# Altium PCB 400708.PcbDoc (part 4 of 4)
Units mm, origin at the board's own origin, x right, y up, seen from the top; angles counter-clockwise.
Board outline 117 x 63.5 mm, 4 copper layers (Top Layer, Mid-Layer 1, Mid-Layer 2, Bottom Layer), stack 1.556 mm thick; 226 components, 168 nets, 912 pads, 2002 vias.
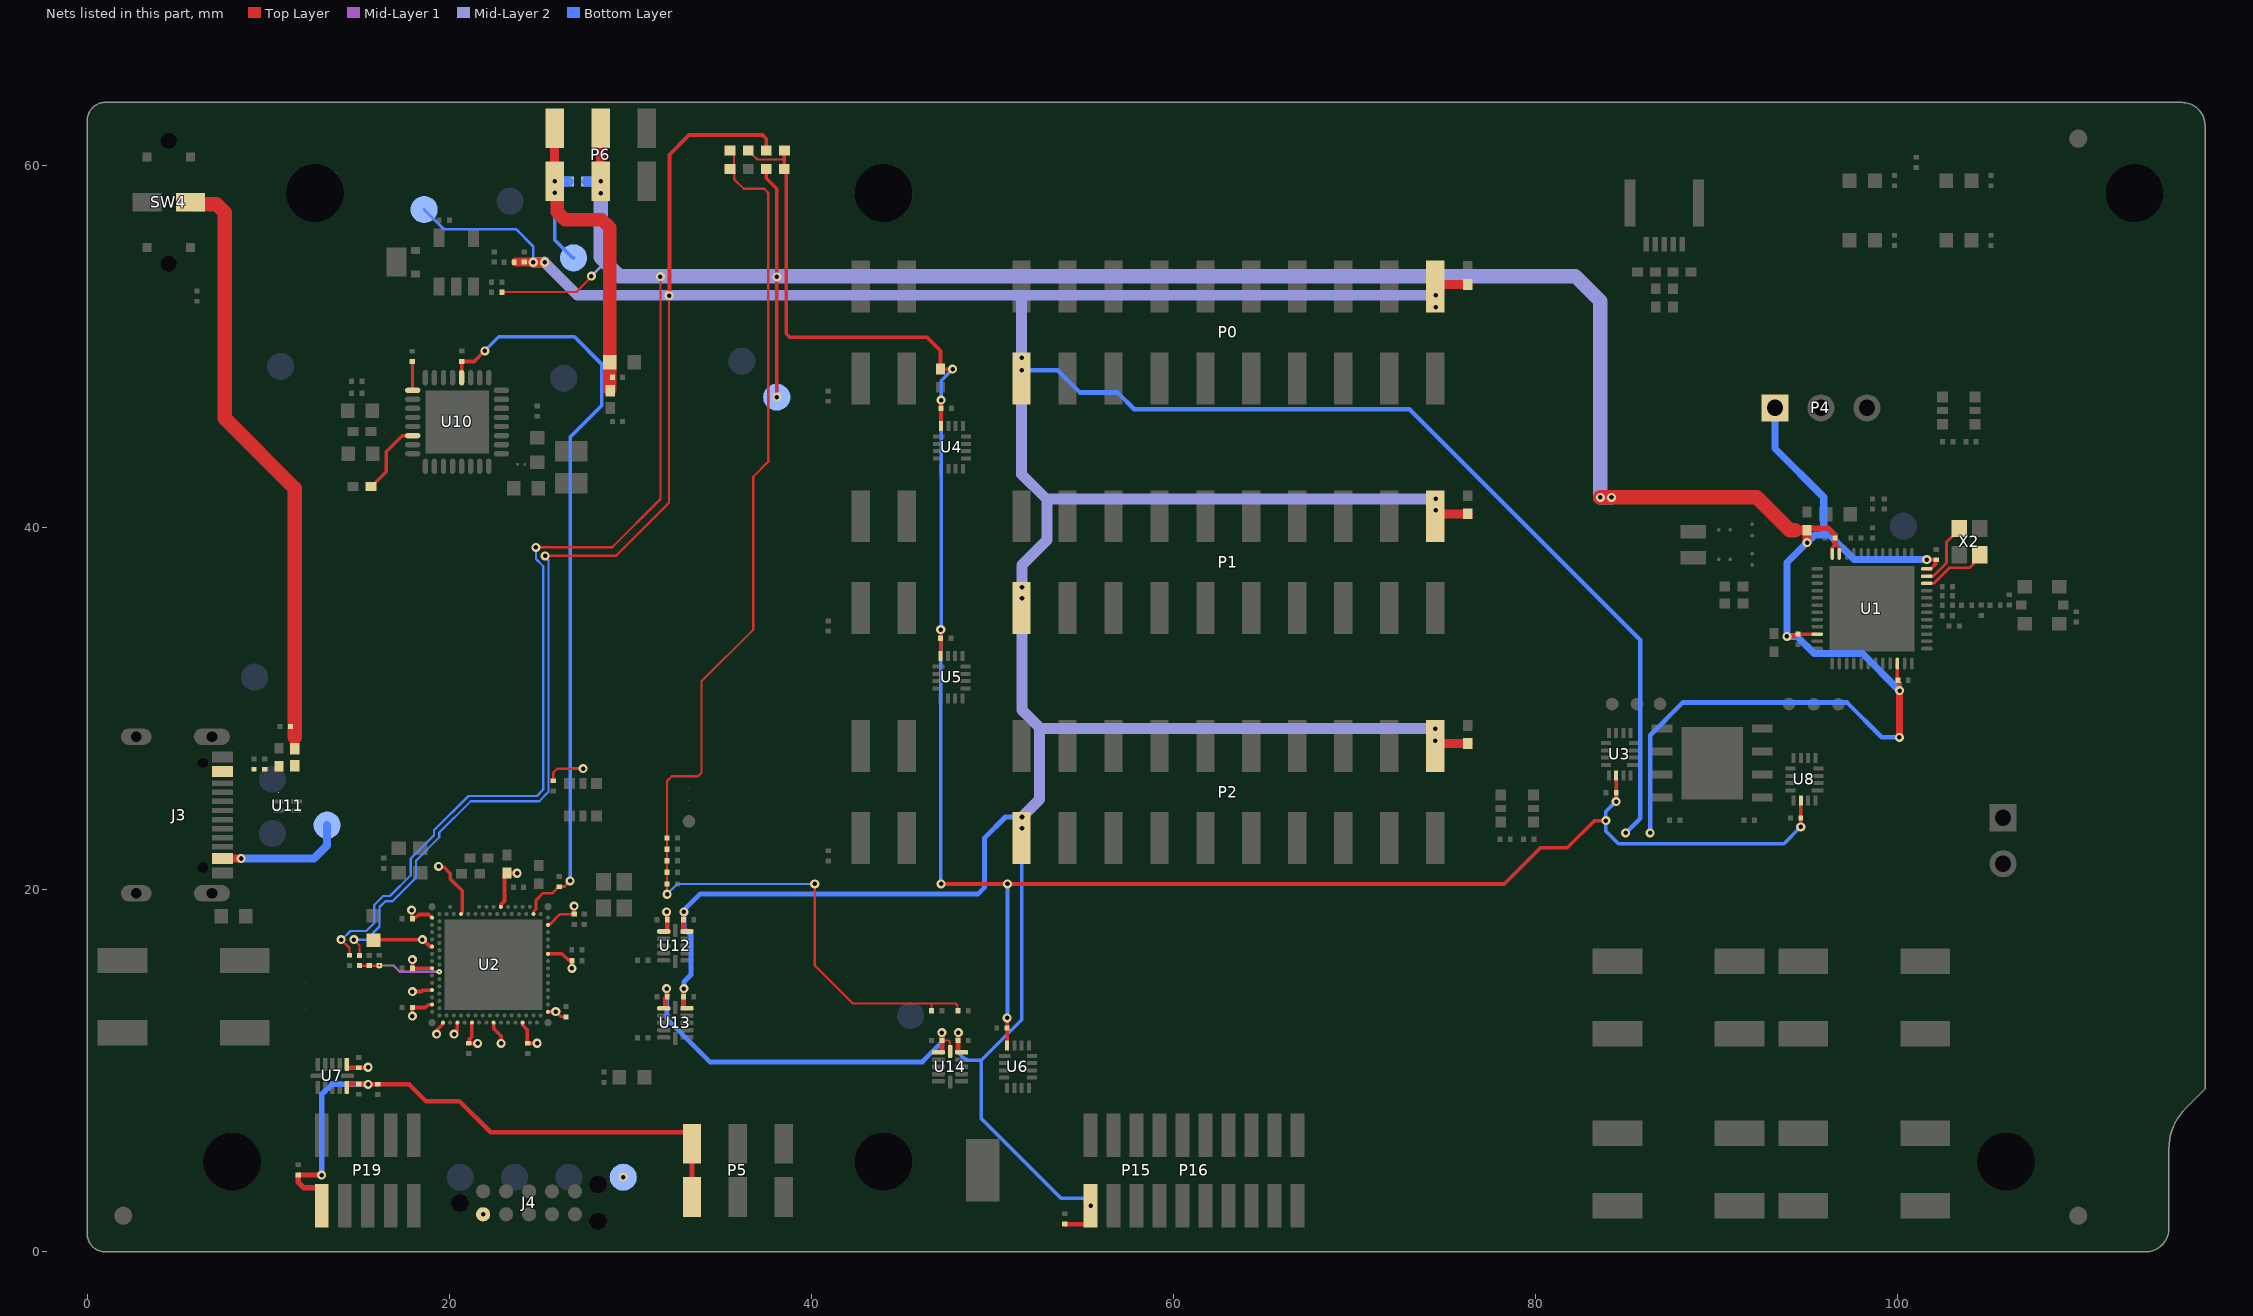
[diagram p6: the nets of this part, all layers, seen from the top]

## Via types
v1: diameter 0.5, hole 0.25, Top Layer to Bottom Layer, tented both sides, 1905 vias
v2: diameter 0.3, hole 0.1, Top Layer to Mid-Layer 1, tented top, 77 vias
v3: diameter 0.3, hole 0.1, Top Layer to Mid-Layer 1, tented both sides, 20 vias

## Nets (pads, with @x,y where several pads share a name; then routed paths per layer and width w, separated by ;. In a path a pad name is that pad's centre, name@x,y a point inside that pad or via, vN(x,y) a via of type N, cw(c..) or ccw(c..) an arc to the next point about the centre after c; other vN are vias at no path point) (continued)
VBUS:IN1: C30.1 C47.2 C48.2 FB2.1 J3.A4 J3.A9 TP16.1 U11.1 | length 7.2
  Top Layer w0.45: J3.A9@7.485,21.734 7.487,21.732 v1(8.517,21.732)
  Bottom Layer w0.45: v1(8.517,21.732) 8.519,21.73 12.548,21.73 13.263,22.446 TP16.1@13.263,23.571
VBUS:IN2: C46.2 FB2.2 SW4.5 | length 33.3
  Top Layer w0.5: FB2.2@11.475,27.8 11.475,28.423
  Top Layer w0.8: SW4.5@5.721,57.988 5.821,57.888 7.131,57.888 7.6,57.42 7.6,46.05 11.475,42.175 11.475,29.025 11.475,28.423
VBUSOUT: C68.2 U10.22 | length 4.1
  Top Layer w0.2: C68.2@15.702,42.275 16.525,43.098 16.525,44.202 17.408,45.086 17.981,45.086 U10.22@17.992,45.096
VDD: C25.2 C58.1 FB3.2 P6.3 R24.2 TP9.1 | length 22.4
  Top Layer w0.3: v1(25.832,58.5) v1(25.832,59.141)
  Top Layer w0.5: v1(25.832,59.141) P6.3@25.832,62.071
  Top Layer w0.75: v1(25.832,58.5) 25.888,58.5 25.967,58.421 25.967,57.464 26.406,57.025 28.436,57.025 28.875,56.586 C58.1@28.875,49.139 ; FB3.2@28.887,47.665 28.887,48.321 C58.1@28.887,49.139
  Bottom Layer w0.2: v1(25.832,58.5) 25.832,55.901 26.818,54.915 TP9.1@26.877,54.915
  Bottom Layer w0.55: v1@25.826,59.141 v1(25.832,59.141) ; v1(25.832,58.5) v1(25.832,59.141) ; R24.2@26.599,59.141 v1(25.832,59.141)
VDD:DBGR: C13.1 C18.1 C20.1 C22.1 C29.1 C31.1 C34.1 C35.1 C36.1 C37.1 C40.1 C53.2 C74.1 C76.1 C78.1 J4.1 R6.2 R8.2 TP3.1 U2.A19 U2.AC1 U2.AG1 U2.AJ31 U2.AL3 U2.AL7 U2.AL11 U2.AL17 U2.AL25 U2.B8 U2.B28 U2.C1 U2.E31 U2.L1 U2.N31 U2.U1 U7.1 U10.12 U12.1 U13.1 U14.1 U14.12 | length 96.4
  Top Layer w0.125: R8.2@25.76,26.025 25.76,26.479 25.975,26.694 v1(27.4,26.694) ; C78.1@47.224,11.679 47.602,11.679 47.675,11.606 U14.12@47.675,11.075
  Top Layer w0.15: U2.B28@24.66,18.664 24.675,18.679 24.675,18.801 24.798,18.925 24.798,19.204 24.798,19.427 25.185,19.815 25.722,19.815 26.081,20.174 C37.1@26.096,20.174 26.11,20.188 26.383,20.188 v1(26.685,20.49) ; U2.E31@25.443,18.079 25.562,18.079 25.824,18.341 25.824,18.364 26.102,18.642 26.125,18.642 26.134,18.651 26.899,18.651 C36.1@26.909,18.661 ; v1(25.893,13.271) 26.173,12.991 26.454,12.991 R6.2@26.46,12.986
  Top Layer w0.187: v1(19.425,21.3) 19.485,21.24 19.735,21.24 20.075,20.9 20.075,20.6 20.735,19.94 20.735,18.75 20.66,18.675 U2.B8@20.66,18.664 ; U2.N31@25.46,16.464 26.236,16.464 26.572,16.128 C35.1@26.691,16.128
  Top Layer w0.2: C40.1@16.018,17.25 v1(18.525,17.25) 18.562,17.25 18.943,16.869 19.055,16.869 U2.L1@19.06,16.864 ; v1(17.925,18.875) 17.949,18.851 17.949,18.426 C13.1@17.974,18.401 17.974,18.416 18.009,18.451 18.134,18.451 18.325,18.642 18.883,18.642 U2.C1@19.06,18.464 ; v1(17.968,13.03) 17.968,13.471 17.98,13.471 18.009,13.499 18.682,13.499 18.842,13.66 19.055,13.66 U2.AG1@19.06,13.664 ; v1(17.968,14.381) 17.976,14.388 18.481,14.388 18.558,14.464 U2.AC1@19.06,14.464 ; C18.1@17.974,15.63 v1@17.974,16.149 ; C18.1@17.979,15.664 U2.U1@19.06,15.664 ; v1(19.314,12.026) 19.372,12.083 19.372,12.296 19.655,12.58 19.655,12.66 U2.AL3@19.66,12.664 ; v1(20.279,12.026) 20.279,12.107 20.46,12.288 U2.AL7@20.46,12.664 ; U10.12@20.7,48.304 C29.1@20.7,49.19 21.39,49.19 v1(21.975,49.775) ; C22.1@21.092,11.524 21.127,11.559 21.13,11.559 21.13,11.759 21.26,11.889 U2.AL11@21.26,12.664 ; C22.1@21.101,11.521 21.572,11.521 v1(21.575,11.518) ; U2.AL17@22.46,12.664 22.46,12.334 22.878,11.916 v1(22.878,11.518) ; U2.AL25@24.06,12.664 24.065,12.66 24.065,12.514 24.318,12.261 24.318,11.549 C34.1@24.343,11.524 24.346,11.521 24.856,11.521 v1(24.86,11.525) ; U2.AJ31@25.46,13.264 25.887,13.264 v1(25.893,13.271) ; C35.1@26.691,16.128 26.748,16.128 26.783,16.093 C35.1@26.783,16.078 v1(26.782,15.659)
  Top Layer w0.203: v1(26.907,19.101) 26.909,19.1 C36.1@26.909,18.661
  Top Layer w0.225: U2.A19@22.86,19.064 22.86,19.179 23.073,19.392 23.073,20.848 C31.1@23.15,20.924 ; C31.1@23.2,20.916 v1(23.759,20.916)
  Top Layer w0.27: U7.1@14.362,10.174 C53.2@15.004,10.174 15.499,10.174 v1(15.525,10.2) ; v1(32.023,14.539) 32.051,14.51 C76.1@32.051,14.104 31.948,14.001 31.948,13.564 U13.1@32.051,13.462 ; v1(32.023,18.789) 32.051,18.76 C74.1@32.051,18.354 U12.1@32.051,17.712 ; U14.1@47.226,11.037 C78.1@47.224,11.679 v1(47.226,12.114)
  Mid-Layer 1 w0.2: v1@21.541,11.484 v1(21.575,11.518) v1@21.632,11.461
  Bottom Layer w0.125: 26.685,26.694 v1(27.4,26.694)
  Bottom Layer w0.2: v1(21.575,11.518) v1@21.656,11.518 ; v1(21.975,49.775) 22.75,50.55 26.925,50.55 28.425,49.05 28.425,46.739 26.685,44.999 26.685,26.694 v1(26.685,20.49)
  Bottom Layer w0.27: v1(32.023,14.539) 32.023,12.876 34.4,10.498 46.148,10.498 47.226,11.576 v1(47.226,12.114)
  other v1: 21.878,2.074 29.62,4.125 17.975,16.15
VDD:IO: C16.2 C28.2 C51.2 C63.2 C75.1 C77.1 C79.1 P0.1 P0.20 P1.1 P1.20 P2.1 P2.20 P15.1 P16.1 R9.2 R25.1 R37.2 R41.2 SB9.1 TP11.1 U12.11 U13.11 U14.11 | length 319.5
  Top Layer w0.125: v1(14.742,17.25) 15.053,16.939 R41.2@15.053,16.384 ; v1(25.3,38.45) 29.209,38.45 32.15,41.391 v1(32.15,52.825)
  Top Layer w0.2: R37.2@24.142,54.675 R37.2@24.144,54.672 ; v1@24.647,54.672 v1(24.65,54.67) ; v1(32.15,52.825) 32.175,52.85 32.175,60.615 33.26,61.7 37.318,61.7 37.525,61.493 R25.1@37.525,60.85
  Top Layer w0.25: C63.2@54,1.54 55.438,1.54 v1(55.438,2.55) ; P0.20@74.484,53.34 P0.20@74.484,54.215 ; v1(74.485,28.243) P2.20@74.485,28.815 ; v1(74.504,40.97) P1.20@74.504,41.515
  Top Layer w0.27: U13.11@32.948,13.514 32.952,14.094 32.952,14.516 v1(32.975,14.539) ; U12.11@32.948,17.764 C75.1@32.948,18.354 v1@32.948,18.789 ; U14.11@48.123,11.089 48.127,11.679 v1(48.13,12.114) C79.1@48.123,11.679
  Top Layer w0.5: R9.2@23.669,54.674 R37.2@24.142,54.675 24.645,54.674 v1@24.647,54.672 ; v1@24.652,54.672 v1(25.278,54.672) ; P0.20@74.484,53.34 74.594,53.45 C28.2@76.275,53.45 ; P2.20@74.594,28.076 C51.2@76.275,28.076 ; P1.20@74.594,40.775 C16.2@76.275,40.775
  Mid-Layer 2 w0.6: v1(24.65,54.67) 24.652,54.672 v1(25.278,54.672) ; v1@25.275,54.675 v1(25.278,54.672) ; v1@32.125,52.85 27.1,52.85 v1(25.278,54.672) ; v1@32.17,52.845 v1(74.51,52.845) v1@74.51,52.21 ; 51.629,52.825 v1(51.629,49.403) v1(51.629,48.712) 51.629,42.961 52.904,41.686 ; v1@51.644,23.4 51.644,23.377 v1@51.649,23.381 ; v1(51.65,23.4) v1(51.65,24.025) 52.625,25 52.625,28.871 ; v1(51.65,36.1) 51.649,29.933 52.677,28.905 ; v1(51.65,36.1) v1(51.65,36.725) 51.65,37.95 53.025,39.325 53.025,41.613 ; 52.709,28.905 v1(74.484,28.905) ; 53.055,41.595 v1(74.504,41.595) v1(74.504,40.97) ; v1(74.485,28.243) v1(74.484,28.905)
  Bottom Layer w0.125: v1(14.742,17.25) 15.438,17.25 16.162,17.974 16.162,19.049 16.488,19.375 16.875,19.375 18.175,20.675 18.175,21.614 19.462,22.901 19.462,23.167 21.195,24.9 24.975,24.9 25.488,25.413 25.488,38.189 25.3,38.377 v1(25.3,38.45)
  Bottom Layer w0.15: TP11.1@18.622,57.582 19.704,56.5 23.7,56.5 24.65,55.55 v1(24.65,54.67)
  Bottom Layer w0.2: v1(48.13,12.114) 48.13,11.009 48.554,10.585 49.4,10.585 ; v1@51.644,24.025 51.644,12.83 49.4,10.585 ; v1(55.438,2.55) 55.03,2.958 53.809,2.958 49.4,7.368 49.4,10.585
  Bottom Layer w0.25: v1(51.629,48.712) 53.613,48.712 54.85,47.475 56.925,47.475 57.85,46.55 73.057,46.55 85.8,33.807 85.8,23.945 v1(84.997,23.142)
  Bottom Layer w0.27: v1(32.975,14.539) 32.979,14.543 32.979,14.92 33.363,15.304 33.363,17.5 32.975,17.889 v1(32.975,18.789) 32.975,18.875 33.875,19.775 49.225,19.775 49.575,20.125 49.575,22.859 50.741,24.025 51.644,24.025 v1(51.65,24.025)
  other v1: 74.5,52.175
VDD:nRF: C3.2 C4.1 C7.1 C8.1 C11.1 P4.1 P6.2 R23.2 R24.1 R28.1 R43.1 SB10.1 TP1.1 U1.10 U1.22 U1.36 U1.47 U1.48 | length 219.6
  Top Layer w0.125: v1(14.04,17.25) 14.5,16.79 R23.2@14.5,16.385 ; R43.1@22.92,53.025 27.025,53.025 v1@27.894,53.894 ; v1(24.8,38.925) 29.013,38.925 31.675,41.587 v1(31.675,53.875)
  Top Layer w0.2: R28.1@37.519,59.83 37.519,59.31 38.104,58.725 v1(38.104,53.863) v1(38.104,47.219) ; C7.1@94.503,34.134 C7.1@94.518,34.134 ; C7.1@94.523,34.13 U1.10@95.58,34.13 ; U1.48@96.405,38.555 96.405,38.906 96.581,39.082 ; C11.1@96.542,39.474 C11.1@96.577,39.439 ; 96.597,39.098 96.805,38.889 U1.47@96.805,38.555 ; C8.1@100.005,31.568 U1.22@100.005,32.505 ; C8.1@100.034,31.518 C8.1@100.034,31.533 ; U1.36@101.63,37.73 101.855,37.73 101.855,37.732 102.114,37.99 C4.1@102.114,38.178 ; v1(101.63,38.244) 101.639,38.235 102.126,38.235 C4.1@102.149,38.213
  Top Layer w0.25: v1(93.909,34.002) 93.931,34.024 94.393,34.024 C7.1@94.503,34.134 ; C8.1@100.034,31.518 100.132,31.42 v1(100.132,31.005)
  Top Layer w0.3: v1(28.372,58.493) v1(28.372,59.141) ; C3.2@95.128,39.966 96.196,39.966 96.581,39.58 96.581,39.082 ; v1@100.125,30.998 v1(100.132,31.005)
  Top Layer w0.4: v1(100.125,28.425) v1@100.125,30.998
  Top Layer w0.5: v1(28.372,59.141) P6.2@28.372,62.071 ; v1(95.017,39.186) C3.2@95.017,39.867
  Top Layer w0.55: 94.35,39.867 C3.2@95.017,39.867
  Top Layer w0.8: v1(83.607,41.68) v1(84.216,41.68) 92.245,41.68 94.058,39.867 94.35,39.867
  Mid-Layer 2 w0.15: v1(27.862,53.9) 28.372,54.41 28.372,54.937
  Mid-Layer 2 w0.8: v1(28.372,59.141) v1(28.372,58.493) 28.372,54.937 29.409,53.9 v1@31.65,53.9 ; v1@31.7,53.9 82.225,53.9 83.607,52.518 v1(83.607,41.68) v1(84.216,41.68)
  Bottom Layer w0.125: v1(14.04,17.25) 14.075,17.25 14.55,17.725 15.425,17.725 15.871,18.171 15.871,19.169 16.367,19.665 16.739,19.665 17.881,20.807 17.881,21.731 19.171,23.021 19.171,23.287 21.075,25.19 24.854,25.19 25.202,25.538 25.202,37.873 24.8,38.275 v1(24.8,38.925)
  Bottom Layer w0.25: v1(86.347,23.142) 86.347,28.547 88.15,30.35 97.225,30.35 99.15,28.425 v1(100.125,28.425)
  Bottom Layer w0.3: 93.909,35.496 93.921,35.484
  Bottom Layer w0.4: P4.1@93.245,46.625 93.245,44.38 95.935,41.69 95.935,39.606 ; v1(93.909,34.002) 94.465,34.002 95.412,33.055 98.081,33.055 v1(100.132,31.005) ; v1@93.909,34.048 93.909,35.496 93.909,38.078 v1(95.017,39.186) 95.437,39.606 95.935,39.606 ; v1@101.603,38.244 97.62,38.244 96.258,39.606 95.935,39.606
  Bottom Layer w0.55: R24.1@27.599,59.141 v1(28.372,59.141) v1(28.372,58.493)
VDD:SW: C10.1 C15.1 C49.1 C50.2 C65.1 C66.1 R25.2 R28.2 R29.2 U3.14 U4.16 U5.16 U6.16 U8.14 | length 118.2
  Top Layer w0.125: R29.2@36.525,60.85 36.55,60.85 36.762,60.638 36.762,60.613 37.034,60.341 38.519,60.341 ; R25.2@38.287,60.638 38.5,60.85 R25.2@38.525,60.85
  Top Layer w0.2: R28.2@38.519,59.83 38.519,60.341 R25.2@38.519,60.836 ; R28.2@38.625,59.83 38.625,50.727 38.827,50.525 46.4,50.525 47.15,49.775 C50.2@47.15,48.769 v1(47.819,48.769) ; U5.16@47.16,32.911 47.16,33.911 47.154,33.917 47.154,34.369 v1(47.16,34.375) ; v1(47.178,20.325) v1(50.849,20.325) 78.288,20.325 80.288,22.325 81.775,22.325 83.275,23.825 v1(83.9,23.825) ; U4.16@47.178,45.612 47.178,46.603 C10.1@47.182,46.607 v1(47.182,47.056) ; U6.16@50.825,11.4 C49.1@50.825,12.369 v1(50.825,12.925) ; v1(84.47,24.878) 84.47,25.365 84.475,25.371 U3.14@84.475,26.325 ; v1(94.67,23.479) 94.67,23.965 94.675,23.971 U8.14@94.675,24.925
  Bottom Layer w0.2: v1@47.164,20.325 47.164,34.371 v1(47.16,34.375) 47.182,34.396 v1(47.182,47.056) 47.182,48.131 v1(47.819,48.769) ; v1(50.825,12.925) 50.849,12.949 v1(50.849,20.325) ; v1@84.462,24.887 83.9,24.325 v1(83.9,23.825) 83.9,23.25 84.6,22.55 93.741,22.55 v1(94.67,23.479)
VDD:SW_PU: R13.1 R14.1 R15.1 R16.1 R17.2 R29.1 R30.1 R31.1 R35.2 | length 68.4
  Top Layer w0.125: v1(32.04,19.756) R13.1@32.04,20.325 R15.1@32.04,21.605 R16.1@32.04,22.237 R35.2@32.04,22.864 ; R35.2@32.04,22.9 32.04,26.015 32.3,26.275 33.75,26.275 33.95,26.475 33.95,31.525 36.8,34.375 36.8,42.828 37.625,43.653 37.625,58.516 37.416,58.725 36.275,58.725 35.751,59.249 35.751,59.617 35.539,59.83 R30.1@35.525,59.83 35.533,59.83 35.746,60.042 35.746,60.638 35.533,60.85 R29.1@35.525,60.85 ; v1(40.2,20.325) 40.2,15.825 42.3,13.725 46.656,13.725 ; R17.2@46.654,13.325 46.654,13.723 46.656,13.725 ; R31.1@48.11,13.325 48.09,13.345 48.09,13.609 47.974,13.725 46.656,13.725
  Bottom Layer w0.125: v1(32.04,19.756) 32.609,20.325 v1(40.2,20.325)
VDD:SWD0: C14.1 C73.2 P5.3 P19.1 R18.2 U7.11 | length 34.7
  Top Layer w0.15: v1(15.525,9.25) v1@15.531,9.256 ; R18.2@16.058,9.256 R18.2@16.064,9.262
  Top Layer w0.25: v1(15.525,9.25) 16.058,9.25 17.8,9.25 18.725,8.325 20.575,8.325 22.3,6.6 33.035,6.6 33.42,6.215 P5.3@33.42,5.965 P5.3@33.42,3.035
  Top Layer w0.27: U7.11@14.411,9.275 14.414,9.277 C14.1@15.004,9.277 15.498,9.277 v1(15.525,9.25)
  Top Layer w0.3: P19.1@12.964,2.55 12.964,3.32 12.734,3.55 11.964,3.55 11.679,3.835 C73.2@11.679,4.246 v1(12.964,4.246)
  Bottom Layer w0.3: v1(12.964,4.246) 12.964,8.689 13.525,9.25 v1(15.525,9.25)
VMEAS_CH1: C67.1 R41.1 R42.2 U2.V2 | length 4.5
  Top Layer w0.125: R41.1@15.053,15.814 16.143,15.814 v2(16.145,15.815)
  Mid-Layer 1 w0.125: v2(16.145,15.815) 16.935,15.815 17.27,15.48 v2(19.46,15.48)
VSET1: R26.1 U10.17 | length 1.9
  Top Layer w0.15: U10.17@17.742,47.665 17.811,47.596 U10.17@17.992,47.596 17.974,47.614 R26.1@17.974,49.183
XC1: U1.34 X2.1 | length 3.6
  Top Layer w0.15: U1.34@101.691,36.94 102.028,36.94 102.875,37.786 103.993,37.786 104.218,38.011 104.218,38.159 X2.1@104.568,38.509
XC2: U1.35 X2.3 | length 3.6
  Top Layer w0.15: U1.35@101.63,37.33 101.64,37.34 102.004,37.34 102.723,38.058 102.723,39.209 103.068,39.554 103.068,39.609 X2.3@103.418,39.959
pads on no net: Fid1.0 Fid2.0 Fid3.0 J3. J3.0 J3.A8 J3.B8 J4.0 J4.6 J4.7 J4.8 J4.9 J7.0 J7.1 J7.3 J7.5 P0.8 P0.9 P0.10 P0.11 P0.12 P0.13 P0.14 P0.15 P0.16 P0.17 P0.18 P1.18 P2.14 P2.15 P2.16 P2.17 P2.18 P5.2 P15.7 P15.8 P16.7 P16.8 P16.11 P16.13 P19.7 P19.8 P19.9 P30.3 P31.3 P32.3 SW4.0 SW4.1 SW4.6 U2. U2.A1 U2.A21 U2.A31 U2.AD2 U2.AE31 U2.AG31 U2.AH2 U2.AK2 U2.AK4 U2.AK6 U2.AK8 U2.AK10 U2.AK12 U2.AK14 U2.AK22 U2.AK24 U2.AK26 U2.AK28 U2.AK30 U2.AL1 U2.AL31 U2.B10 U2.D2 U2.F2 U2.J1 U2.K2 U2.M2 U2.P2 U2.T2 U2.Y2 U4.7 U4.12 U5.7 U5.12 U6.7 U6.12 U10.5 U10.7 U10.9 U10.10 U10.11 U10.15 U10.18 U10.19 U10.25 U10.26 U10.27 U11.4

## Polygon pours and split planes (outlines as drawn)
P5V0 on Top Layer "P5V0" (solid, remove dead copper, pour order 0): 16.496,48.5 16.496,50.01 17.748,51.263 17.748,59.646 17.294,60.1 14.15,60.1 10.475,56.425 10.475,49.451 11.426,48.5
GND on Top Layer "GND_island" (solid, pour order 4): 103.874,35.423 103.874,34.914 104.306,34.482 104.991,34.482 105.397,34.888 105.397,35.422
GND on Top Layer "Top_Layer-GND" (solid, remove dead copper, pour order 10): 0.002,0.009 0.002,63.509 117.004,63.509 117.004,0.009
GND on Mid-Layer 1 "Mid_Layer1-GND" (solid, remove dead copper, pour order 1): 0.029,0 0.029,63.22 117.004,63.22 117.004,0
GND on Bottom Layer "Bottom_Layer-GND" (solid, remove dead copper, pour order 3): 0.029,0 0.029,63.5 117.004,63.5 117.004,0
VDD:DBGR on Mid-Layer 2 "VDD_DBGR" (solid, pour order 6): 21.754,1.825 25.2,1.825 26.025,2.65 29.176,2.65 30.011,3.485 30.011,4.789 28.85,5.95 28.85,11 32.25,14.4 32.25,18.875 29.675,21.45 19,21.45 17.725,20.175 17.725,14.809 15.175,12.259 15.175,10.025 15.325,9.875 21.219,3.981 21.219,2.36
GND on Mid-Layer 2 "Mid_Layer2-GND" (solid, remove dead copper, pour order 7): 0.029,0 0.029,63.5 117.004,63.5 117.004,0

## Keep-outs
Top Layer:
  region: 112,26.473 cw(c112,29.973) 108.5,29.973 cw(c112,29.973) 112,33.473 cw(c112,29.973) 115.5,29.973 cw(c112,29.973)
  region: 108.496,6.473 cw(c108.496,9.973) 104.996,9.973 cw(c108.496,9.973) 108.496,13.473 cw(c108.496,9.973) 111.996,9.973 cw(c108.496,9.973)
  region: 42.496,14.473 cw(c42.496,17.973) 38.996,17.973 cw(c42.496,17.973) 42.496,21.473 cw(c42.496,17.973) 45.996,17.973 cw(c42.496,17.973)
  region: 74.996,0.473 cw(c74.996,3.973) 71.496,3.973 cw(c74.996,3.973) 74.996,7.473 cw(c74.996,3.973) 78.496,3.973 cw(c74.996,3.973)
  region: 3.496,-0.027 cw(c3.496,3.473) -0.004,3.473 cw(c3.496,3.473) 3.496,6.973 cw(c3.496,3.473) 6.996,3.473 cw(c3.496,3.473)
  region: 20.496,33.473 cw(c20.496,36.973) 16.996,36.973 cw(c20.496,36.973) 20.496,40.473 cw(c20.496,36.973) 23.996,36.973 cw(c20.496,36.973)
  region: 16.496,56.973 cw(c16.496,60.473) 12.996,60.473 cw(c16.496,60.473) 16.496,63.973 cw(c16.496,60.473) 19.996,60.473 cw(c16.496,60.473)
  region: 35.496,52.473 cw(c35.496,55.973) 31.996,55.973 cw(c35.496,55.973) 35.496,59.473 cw(c35.496,55.973) 38.996,55.973 cw(c35.496,55.973)
  region: 77.796,54.973 cw(c77.796,58.473) 74.296,58.473 cw(c77.796,58.473) 77.796,61.973 cw(c77.796,58.473) 81.296,58.473 cw(c77.796,58.473)
  region: 46.352,19.687 ccw(c49.352,19.687) 49.352,16.687 ccw(c49.352,19.687) 52.352,19.687 ccw(c49.352,19.687) 49.352,22.687 ccw(c49.352,19.687)
  region: 8.004,2 cw(c8.004,5) 5.004,5 cw(c8.004,5) 8.004,8 cw(c8.004,5) 11.004,5 cw(c8.004,5)
  region: 44.004,2 cw(c44.004,5) 41.004,5 cw(c44.004,5) 44.004,8 cw(c44.004,5) 47.004,5 cw(c44.004,5)
  region: 106.005,1.979 cw(c106.005,4.979) 103.005,4.979 cw(c106.005,4.979) 106.005,7.979 cw(c106.005,4.979) 109.005,4.979 cw(c106.005,4.979)
  region: 98.967,25.576 cw(c98.967,28.576) 95.967,28.576 cw(c98.967,28.576) 98.967,31.576 cw(c98.967,28.576) 101.967,28.576 cw(c98.967,28.576)
  region: 113.104,55.5 cw(c113.104,58.5) 110.104,58.5 cw(c113.104,58.5) 113.104,61.5 cw(c113.104,58.5) 116.104,58.5 cw(c113.104,58.5)
  region: 44.004,55.5 cw(c44.004,58.5) 41.004,58.5 cw(c44.004,58.5) 44.004,61.5 cw(c44.004,58.5) 47.004,58.5 cw(c44.004,58.5)
  region: 16.439,59.569 cw(c16.439,62.569) 13.439,62.569 cw(c16.439,62.569) 16.439,65.569 cw(c16.439,62.569) 19.439,62.569 cw(c16.439,62.569)
Keep-Out Layer:
  circle w0.152: c12.604,58.5 r2.4
  circle w0.152: c113.104,58.5 r2.4
  circle w0.152: c113.104,58.5 r2.4
  circle w0.152: c106.004,5 r2.4
  circle w0.152: c44.004,5 r2.4
  circle w0.152: c44.004,58.5 r2.4
  circle w0.152: c8.004,5 r2.4

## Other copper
Top Layer:
  rectangle net GND: 6.919,27.025 8.804,27.85
  rectangle net GND: 109.224,34.036 110.038,34.931
  rectangle net GND: 6.891,20.422 8.776,21.247
  rectangle net ANT: 115.025,16.986 116.295,17.748
  pour cut-out: 8.2,23.75 10.573,23.75 10.573,24.279 8.2,24.279 8.2,24.047
  pour cut-out: 25.839,43.656 25.839,43.016 27.809,43.016 27.809,43.656
  region net RF: 106.555,35.98 106.35,35.865 106.35,35.595 106.555,35.48
  region net PVSS1: 22.892,44.446 23.264,44.446 23.499,44.211 23.499,43.936 23.199,43.636 23.199,41.786 23.949,41.786 23.949,42.536 24.65,43.237 25.267,43.237 25.267,43.996 24.164,43.996 23.414,44.746 22.892,44.746
  region net P5V0: 15.382,45.946 15.382,48.629 17.367,48.629 17.367,46.334 17.454,46.246 18.042,46.246 18.042,45.946
  region net NetC27_2: 24.549,42.586 25.69,42.586 25.817,42.713 25.817,43.016 27.652,43.016 27.652,41.589 27.474,41.411 24.549,41.411
  region net P5V0: 23.603,45.459 24.467,44.596 25.267,44.596 25.267,46.296 24.167,46.296 23.604,45.733
  region net NetC59_1: 7.89,19.8 7.89,18.1 5.902,18.1 5.902,19.8
  pour cut-out: 103.874,35.423 103.874,34.914 104.306,34.482 104.991,34.482 105.398,34.889 105.397,34.889 105.397,35.423 105.547,35.423 105.547,34.802 105.065,34.32 104.227,34.32 103.719,34.828 103.719,35.423
  region net VBUS:IN1: 11.725,27.175 11.725,26.525 10.879,26.525 10.879,25.283 10.101,25.283 9.725,25.659 9.725,26.15 9.641,26.234 6.876,26.234 6.719,26.077 6.719,22.178 6.864,22.034 8.059,22.034 8.059,21.434 6.873,21.434 5.95,22.357 5.95,25.875 6.909,26.834 9.937,26.834 10.232,26.539 10.232,25.828 10.577,25.483 10.679,25.483 10.679,25.554 10.35,25.883 10.35,27.175
  region net NetL2_1: 102.387,35.879 101.998,35.829 101.998,35.63 102.387,35.579
  pour cut-out: 99.09,39.615 98.278,39.615 98.278,41.467 99.09,41.467
  pour cut-out: 96.858,41.292 96.649,41.292 96.649,41.179 96.858,41.179
  pour cut-out: 105.311,40.732 105.311,37.477 102.443,37.477 102.443,40.732
  pour cut-out: 102.811,36.895 102.811,36.591 102.923,36.591 102.923,36.895
Mid-Layer 1:
  pour cut-out: 33.851,25.048 32.651,25.048 32.651,25.54 33.851,25.54
  pour cut-out: 85.597,23.262 84.397,23.262 84.397,23.754 85.597,23.754
  pour cut-out: 110.038,37.125 106.927,37.125 106.302,36.5 102.775,36.5 102.775,35.324 103.7,35.324 103.7,34.95 106.302,34.95 106.927,34.325 110.038,34.325
  pour cut-out: 103.719,35.318 103.719,34.828 104.227,34.32 105.065,34.32 105.547,34.802 105.547,35.318
  pour cut-out: 89.779,39.161 89.779,40.616 91.141,40.616 91.141,39.161
  pour cut-out: 89.779,37.535 89.779,38.991 91.141,38.991 91.141,37.535
  pour cut-out: 12.225,12.775 12.225,13.975 12.717,13.975 12.717,12.775
Mid-Layer 2:
  region net P5V0: 25.168,45.289 25.278,45.415 25.278,46.113 22.766,48.625 16.8,48.625 16.8,47.005 16.93,46.875 18.454,46.875 19.029,47.45 21.896,47.45 22.125,47.221 22.125,45.396 22.233,45.287
  pour cut-out: 110.038,37.125 106.927,37.125 106.302,36.5 102.775,36.5 102.775,35.324 103.7,35.324 103.7,34.95 106.302,34.95 106.927,34.325 110.038,34.325
  pour cut-out: 103.719,35.318 103.719,34.828 104.227,34.32 105.065,34.32 105.547,34.802 105.547,35.318
Bottom Layer:
  pour cut-out: 19.572,57.582 cw(c18.62,57.582) 18.62,56.63 cw(c18.62,57.578) 17.672,57.578 17.672,57.589 cw(c18.613,57.589) 18.613,58.53 18.623,58.53 cw(c18.623,57.582)
  pour cut-out: 16.397,44.858 cw(c15.446,44.858) 15.446,43.906 cw(c15.446,44.854) 14.498,44.854 14.498,44.865 cw(c15.439,44.865) 15.439,45.806 15.449,45.806 cw(c15.449,44.858)
  pour cut-out: 20.072,29.999 cw(c19.12,29.999) 19.12,29.047 cw(c19.12,29.995) 18.172,29.995 18.172,30.006 cw(c19.113,30.006) 19.113,30.947 19.124,30.947 cw(c19.124,29.999)
  pour cut-out: 10.085,12.152 cw(c9.133,12.152) 9.133,11.2 cw(c9.133,12.149) 8.185,12.149 8.185,12.159 cw(c9.126,12.159) 9.126,13.1 9.137,13.1 cw(c9.137,12.152)
  pour cut-out: 23.027,54.815 cw(c22.075,54.815) 22.075,53.863 cw(c22.075,54.811) 21.127,54.811 21.127,54.822 cw(c22.068,54.822) 22.068,55.763 22.079,55.763 cw(c22.079,54.815)
  pour cut-out: 15.483,54.307 cw(c14.531,54.307) 14.531,53.355 cw(c14.531,54.303) 13.583,54.303 13.583,54.314 cw(c14.524,54.314) 14.524,55.255 14.535,55.255 cw(c14.535,54.307)
  pour cut-out: 32.984,37.568 cw(c32.032,37.568) 32.032,36.617 cw(c32.032,37.565) 31.084,37.565 31.084,37.576 cw(c32.025,37.576) 32.025,38.517 32.036,38.517 cw(c32.036,37.568)
  pour cut-out: 38.368,38.713 cw(c37.417,38.713) 37.417,37.761 cw(c37.417,38.71) 36.469,38.71 36.469,38.72 cw(c37.41,38.72) 37.41,39.661 37.42,39.661 cw(c37.42,38.713)
  pour cut-out: 39.869,42.397 cw(c38.918,42.397) 38.918,41.445 cw(c38.918,42.393) 37.969,42.393 37.969,42.404 cw(c38.911,42.404) 38.911,43.345 38.921,43.345 cw(c38.921,42.397)
  pour cut-out: 27.284,48.262 cw(c26.332,48.262) 26.332,47.31 cw(c26.332,48.258) 25.384,48.258 25.384,48.269 cw(c26.325,48.269) 26.325,49.21 26.336,49.21 cw(c26.336,48.262)
  pour cut-out: 14.213,38.847 cw(c13.261,38.847) 13.261,37.895 cw(c13.261,38.843) 12.313,38.843 12.313,38.854 cw(c13.254,38.854) 13.254,39.795 13.265,39.795 cw(c13.265,38.847)
  pour cut-out: 11.19,41.354 cw(c10.239,41.354) 10.239,40.403 cw(c10.239,41.351) 9.291,41.351 9.291,41.362 cw(c10.232,41.362) 10.232,42.303 10.242,42.303 cw(c10.242,41.354)
  pour cut-out: 11.19,38.354 cw(c10.239,38.354) 10.239,37.403 cw(c10.239,38.351) 9.291,38.351 9.291,38.362 cw(c10.232,38.362) 10.232,39.303 10.242,39.303 cw(c10.242,38.354)
  pour cut-out: 16.982,27.612 cw(c16.03,27.612) 16.03,26.66 cw(c16.03,27.608) 15.082,27.608 15.082,27.619 cw(c16.023,27.619) 16.023,28.56 16.034,28.56 cw(c16.034,27.612)
  pour cut-out: 22.747,27.434 cw(c21.796,27.434) 21.796,26.482 cw(c21.796,27.43) 20.848,27.43 20.848,27.441 cw(c21.789,27.441) 21.789,28.382 21.799,28.382 cw(c21.799,27.434)
  pour cut-out: 25.747,28.424 cw(c24.796,28.424) 24.796,27.473 cw(c24.796,28.421) 23.848,28.421 23.848,28.432 cw(c24.789,28.432) 24.789,29.373 24.799,29.373 cw(c24.799,28.424)
  pour cut-out: 28.747,28.424 cw(c27.796,28.424) 27.796,27.473 cw(c27.796,28.421) 26.848,28.421 26.848,28.432 cw(c27.789,28.432) 27.789,29.373 27.799,29.373 cw(c27.799,28.424)
  pour cut-out: 38.165,26.748 cw(c37.213,26.748) 37.213,25.796 cw(c37.213,26.744) 36.265,26.744 36.265,26.755 cw(c37.206,26.755) 37.206,27.696 37.217,27.696 cw(c37.217,26.748)
  pour cut-out: 38.165,21.748 cw(c37.213,21.748) 37.213,20.796 cw(c37.213,21.744) 36.265,21.744 36.265,21.755 cw(c37.206,21.755) 37.206,22.696 37.217,22.696 cw(c37.217,21.748)
  pour cut-out: 38.165,16.748 cw(c37.213,16.748) 37.213,15.796 cw(c37.213,16.744) 36.265,16.744 36.265,16.755 cw(c37.206,16.755) 37.206,17.696 37.217,17.696 cw(c37.217,16.748)
  pour cut-out: 38.165,11.748 cw(c37.213,11.748) 37.213,10.796 cw(c37.213,11.744) 36.265,11.744 36.265,11.755 cw(c37.206,11.755) 37.206,12.696 37.217,12.696 cw(c37.217,11.748)
Multi-Layer:
  pour cut-out: 110.035,0.028 117.023,0.028 116.971,63.5 110.041,63.5

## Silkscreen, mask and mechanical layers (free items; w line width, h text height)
Top Overlay:
  circle w0.15: c80.975,30.275 r1.13
  circle w0.15: c27.1,57.087 r0.884
  region: 79.619,29.08 79.619,30.304 cw(c80.99,30.304) 81.005,31.675 81.005,31.405 ccw(c80.994,30.35) 79.94,30.35 79.94,30.199 ccw(c80.994,30.199) 80.994,29.145 80.994,29.08
  region: 82.37,29.08 82.37,30.305 ccw(c81,30.304) 80.995,31.675 80.995,31.405 cw(c80.995,30.35) 82.05,30.35 82.05,30.2 cw(c80.995,30.2) 80.995,29.145 80.995,29.081
  region: 29.212,56.075 28.513,55.183 27.838,56.075
  region: 24.975,55.203 25.675,56.095 26.35,55.203
  lines w0.15: 15.875,41.75 15.875,40.767 29.075,40.767 29.075,45.4 ; 15.875,47.175 15.875,50.261 29.07,50.261 29.07,49.85 ; 15.879,15.3 15.879,11.244 20.675,11.244 ; 15.879,19.375 15.879,23.05 29.077,23.05 29.078,21.174 ; 21.539,11.244 23.851,11.244 ; 24.841,11.244 29.078,11.244 ; 29.075,11.244 29.075,18.288 ; 30.15,56.35 31.65,56.35 ; 30.45,56.1 31.35,56.1 ; 30.7,55.855 31.1,55.855 ; 30.9,56.35 30.9,57.1 ; 42.204,29.8 42.204,30.3 42.45,30.3 ; 42.204,42.5 42.204,43 42.45,43 ; 42.204,55.2 42.204,55.7 42.45,55.7 ; 45.559,30.3 45.804,30.3 45.804,29.8 ; 45.559,43 45.804,43 45.804,42.5 ; 45.559,55.7 45.804,55.7 45.804,55.2 ; 105.875,35.1 105.875,31.1 94,31.1 94,39.125 94,42.125 101.489,42.125 105.875,42.125 105.875,36.725
  lines w0.178: 25.668,56.32 25.668,56.5 ; 25.668,56.785 25.668,57.098 25.925,57.098 ; 28.275,57.1 28.525,57.1 28.525,56.787 ; 28.525,56.308 28.525,56.489
  lines w0.381: 54.103,0.699 cw(c54.183,0.6) 54.263,0.699
  text "ON" at 0.35,61.3 h1.4
  text "NFC" at 83.126,59.729 h1.8
  text "LED0" at 96.062,59.727 h1.8
  text "LED1" at 101.887,59.727 h1.8
  text "GPIO pins shown in parentheses are only available on headers with modification" at 50.325,59.25 h1.6
  text "VDD / CURRENT / MEASURE" at 16.649,58.208 h1.8
  text "A" at 26.65,56.65 h1.52
  text "LED2" at 96.087,56.427 h1.8
  text "LED3" at 101.887,56.427 h1.8
  text "GND" at 42.63,55.215 h1.52
  text "GND" at 49.725,55.2 h1.52
  text "01" at 53.565,55.209 h1.52
  text "03" at 55.965,55.209 h1.52
  text "VDD:IO" at 72.625,55.2 h1.52
  text "POWER" at 8.575,54.488 h1.8 r90
  text "OFF" at 0.35,53.425 h1.4
  text "IDD" at 26.125,52.9 h1.52 r90
  text "GND" at 31.375,52.125 h1.52 r90
  text "nRF54" at 28.925,51.4 h1.52 r90
  text "VDD:nRF" at 93.625,47.988 h1.27 r90
  text "DECD" at 96.181,47.964 h1.27 r90
  text "GND" at 98.708,47.964 h1.27 r90
  text "PORT P0" at 50.023,46.672 h1.8 r90
  text "P5V0" at 40.261,45.469 h1.52
  text "VDD:IO" at 48.625,45.475 h1.52
  text "00" at 53.487,45.475 h1.52
  text "02" at 56.008,45.47 h1.52
  text "04" at 58.548,45.47 h1.52
  text "GND" at 73.35,45.475 h1.52
  text "GND" at 42.63,42.515 h1.52
  text "GND" at 49.716,42.5 h1.52
  text "09" at 63.687,42.5 h1.52
  text "11" at 66.562,42.5 h1.52
  text "13" at 68.962,42.5 h1.52
  text "VDD:IO" at 72.625,42.5 h1.52
  text "05" at 58.523,42.493 h1.52
  text "07" at 61.063,42.493 h1.52
  text "(01)" at 53.25,42.25 h1.52
  text "(03)" at 55.625,42.25 h1.52
  text "nRF54L15" at 93.93,42.15 h1.8
  text "PMIC" at 15.799,39.042 h1.8
  text ".PCBNumber" at 0.598,38.543 h2.03
  text ".PCBRevision" at 0.598,37.381 h1.52
  text "PORT P1" at 50.023,33.972 h1.8 r90
  text "nRF54L15-DK" at 0.515,33.45 h3
  text "P5V0" at 40.261,32.769 h1.52
  text "VDD:IO" at 48.65,32.725 h1.52
  text "04" at 58.548,32.72 h1.52
  text "06" at 61.088,32.72 h1.52
  text "08" at 63.628,32.72 h1.52
  text "10" at 66.345,32.72 h1.52
  text "12" at 68.937,32.725 h1.52
  text "14" at 71.425,32.72 h1.52
  text "GND" at 73.287,32.725 h1.52
  text "(02)" at 55.675,32.475 h1.52
  text "(00)" at 53.075,32.45 h1.52
  text "VDD:IO" at 72.625,29.85 h1.52
  text "05" at 58.504,29.825 h1.52
  text "09" at 63.675,29.825 h1.52
  text "GND" at 42.63,29.815 h1.52
  text "GND" at 49.725,29.8 h1.52
  text "01" at 53.529,29.809 h1.52
  text "03" at 55.929,29.809 h1.52
  text "07" at 61.262,29.8 h1.52
  text "DEBUGGER" at 0.587,29.149 h1.8
  text "GND" at 79.619,27.898 h1.4
  text "nRF54" at 107.1,24.15 h1.27
  text "RESET" at 107.1,23.125 h1.27
  text "DEBUGGER" at 15.813,23.05 h1.8
  text "PORT P2" at 50.023,21.272 h1.8 r90
  text "GND" at 107.1,21.054 h1.27
  text "P5V0" at 40.261,20.069 h1.52
  text "VDD:IO" at 48.65,20.075 h1.52
  text "00" at 53.45,20.075 h1.52
  text "02" at 55.971,20.07 h1.52
  text "04" at 58.511,20.07 h1.52
  text "06" at 61.088,20.02 h1.52
  text "08" at 63.628,20.02 h1.52
  text "10" at 66.362,20.025 h1.52
  text "GND" at 73.275,20.025 h1.52
  text "BUTTON 0" at 83.896,17.287 h1.8
  text "BUTTON 1" at 94.146,17.287 h1.8
  text "RESET" at 1.397,9.242 h1.8
  text "DEBUG IN/ TRACE" at 56.9,7.85 h1.8
  text "BUTTON 2" at 83.896,7.786 h1.8
  text "BUTTON 3" at 94.158,7.786 h1.8
  text "GND" at 38.975,7.7 h1.52 r90
  text "VDD / SWD0" at 35,7.206 h1.52 r90
  text "GND" at 48.109,6.577 h1.4
  text "DEBUG OUT" at 3.35,1.325 h1.8
  text "GND" at 48.103,1.123 h1.4
  text "3.6V Max" at 13.05,0.325 h1.4
Bottom Overlay:
  drawing of 375 lines, arcs and shapes, not listed
  text "220-JP8930" at 7.92,52.576 h1.5 r180
  text "P2.00" at 52.359,51.589 h1.91 r180
  text "DIO3" at 59.522,51.589 h1.91 r180
  text "P2.03" at 52.359,48.896 h1.91 r180
  text "DIO2" at 59.547,48.897 h1.91 r180
  text "MEM" at 74.067,48.406 h1.78 r180
  text "P2.04" at 52.359,46.204 h1.91 r180
  text "DIO1" at 59.624,46.204 h1.91 r180
  text "GPIO" at 66.343,44.955 h1.78 r180
  text "P2" at 76.06,43.654 h1.78 r180
  text "P2.02" at 52.384,43.512 h1.91 r180
  text "DIO0" at 59.522,43.488 h1.91 r180
  text "P2.07" at 27.025,41.589 h1.91 r180
  text "SWO" at 34.292,41.601 h1.91 r180
  text "nRF54" at 41.782,41.441 h2.03 r180
  text "DEBUGGER" at 68.931,41.349 h1.4 r180
  text "P2.01" at 52.359,40.819 h1.91 r180
  text "CLK" at 59.674,40.819 h1.91 r180
  text "SWDCLK" at 32.746,39.126 h1.91 r180
  text "P2.05" at 52.359,38.127 h1.91 r180
  text "CS" at 60.284,38.127 h1.91 r180
  text "SWDIO" at 33.493,36.576 h1.91 r180
  text "GPIO" at 51.936,36.054 h1.99 r180
  text "Function" at 57.407,36.054 h1.99 r180
  text "Circuit" at 69.514,35.603 h2.03 r180
  text "DEBUGGER" at 42.334,35.375 h1.4 r180
  text "RESET" at 34.15,33.976 h1.91 r180
  text "BUTTON 3" at 87.496,33.131 h1.91 r180
  text "P0.04" at 82.331,32.511 h1.91 r180
  text "GPIO" at 73.074,31.919 h1.78 r180
  text "P1.07" at 27.042,31.521 h1.91 r180
  text "CTS1" at 34.501,31.527 h1.91 r180
  text "NFC2" at 59.269,30.94 h1.91 r180
  text "P1.03" at 52.309,30.916 h1.91 r180
  text "BUTTON 2" at 87.521,30.46 h1.91 r180
  text "P1.08" at 82.332,29.811 h1.91 r180
  text "0R" at 76.796,29.57 h1.52 r180
  text "P1.06" at 27.042,28.981 h1.91 r180
  text "RTS1" at 34.594,28.987 h1.91 r180
  text "N.C." at 73.171,28.88 h1.52 r180
  text "nRF54" at 41.829,28.413 h2.03 r180
  text "NFC" at 77.938,27.873 h1.78 r180
  text "BUTTON 1" at 87.521,27.756 h1.91 r180
  text "P1.09" at 82.327,27.134 h1.91 r180
  text "P1.04" at 27.042,26.441 h1.91 r180
  text "TXD1" at 34.359,26.442 h1.91 r180
  text "NFC1" at 59.371,25.785 h1.91 r180
  text "P1.02" at 52.309,25.76 h1.91 r180
  text "GPIO" at 96.048,25.636 h1.78 r180
  text "BUTTON 0" at 87.488,25.105 h1.91 r180
  text "PIN" at 74.992,24.777 h1.78 r180
  text "PIN" at 41.681,24.413 h1.78 r180
  text "P1.13" at 82.332,24.411 h1.91 r180
  text "P1.05" at 27.042,23.901 h1.91 r180
  text "RXD1" at 34.347,23.902 h1.91 r180
  text "SB6" at 66.343,21.797 h1.91 r180
  text "P1.14" at 82.327,21.749 h1.91 r180
  text "LED 3" at 89.058,21.736 h1.91 r180
  text "P0.03" at 27.042,21.362 h1.91 r180
  text "CTS0" at 34.234,21.368 h1.91 r180
  text "P1.01" at 52.373,20.411 h1.91 r180
  text "XL2" at 59.892,20.389 h1.91 r180
  text "1M" at 97.086,20.172 h1.52 r180
  text "GPIO" at 73.074,19.375 h1.78 r180
  text "SB4" at 66.343,19.105 h1.91 r180
  text "P2.07" at 82.327,19.057 h1.91 r180
  text "LED 2" at 89.058,19.057 h1.91 r180
  text "P0.02" at 27.042,18.822 h1.91 r180
  text "RTS0" at 34.326,18.828 h1.91 r180
  text "GPIO" at 96.057,17.523 h1.78 r180
  text "DEBUGGER" at 42.379,16.9 h1.4 r180
  text "SB5" at 66.343,16.413 h1.91 r180
  text "P1.10" at 82.327,16.364 h1.91 r180
  text "LED 1" at 89.058,16.341 h1.91 r180
  text "P0.00" at 27.042,16.283 h1.91 r180
  text "TXD0" at 34.091,16.272 h1.91 r180
  text "P1.00" at 52.373,15.026 h1.91 r180
  text "XL1" at 59.993,15.004 h1.91 r180
  text "PIN" at 78.434,14.827 h1.78 r180
  text "LED 0" at 89.07,14.474 h1.91 r180
  text "P0.01" at 27.042,13.743 h1.91 r180
  text "RXD0" at 34.079,13.732 h1.91 r180
  text "SB3" at 66.343,13.72 h1.91 r180
  text "P2.09" at 82.327,13.672 h1.91 r180
  text "P5V0" at 100.398,13.25 h1.52 r180
  text "GPIO" at 51.916,11.631 h1.99 r180
  text "Function" at 57.408,11.631 h1.99 r180
  text "Short" at 66.394,11.631 h1.99 r180
  text "HW" at 74.979,11.606 h1.99 r180
  text "GPIO" at 81.904,11.584 h1.99 r180
  text "Function" at 87.375,11.584 h1.99 r180
  text "HW" at 97.853,11.569 h1.99 r180
  text "GPIO" at 27.016,11.191 h2.03 r180
  text "Function" at 32.899,11.188 h2.03 r180
  text "Circuit" at 43.32,11.182 h2.03 r180
Top Paste:
  circle w1.1: c80.975,30.275 r0.25
Top Solder:
  circle w1.4: c80.975,30.275 r0.25
Board Outline:
  the board outline again, w0.254
PCB Info:
  circle w0.013: c113.104,58.5 r3
  circle w0.013: c113.104,58.5 r3
  circle w0.013: c113.104,58.5 r3
  circle w0.013: c113.104,58.5 r3
  circle w0.013: c113.104,58.5 r3
  circle w0.013: c113.104,58.5 r3
  circle w0.013: c98.969,28.576 r3
  circle w0.013: c98.969,28.576 r3
  circle w0.013: c98.969,28.576 r3
  circle w0.013: c98.969,28.576 r3
  circle w0.013: c98.969,28.576 r3
  circle w0.013: c98.969,28.576 r3
  circle w0.013: c106.004,5 r3
  circle w0.013: c106.004,5 r3
  circle w0.013: c106.004,5 r3
  circle w0.013: c106.004,5 r3
  circle w0.013: c106.004,5 r3
  circle w0.013: c106.004,5 r3
  circle w0.013: c44.004,5 r3
  circle w0.013: c44.004,5 r3
  circle w0.013: c44.004,5 r3
  circle w0.013: c44.004,5 r3
  circle w0.013: c44.004,5 r3
  circle w0.013: c44.004,5 r3
  circle w0.013: c49.35,19.687 r3
  circle w0.013: c49.35,19.687 r3
  circle w0.013: c49.35,19.687 r3
  circle w0.013: c49.35,19.687 r3
  circle w0.013: c49.35,19.687 r3
  circle w0.013: c49.35,19.687 r3
  circle w0.013: c8.004,5 r3
  circle w0.013: c8.004,5 r3
  circle w0.013: c8.004,5 r3
  circle w0.013: c8.004,5 r3
  circle w0.013: c8.004,5 r3
  circle w0.013: c8.004,5 r3
  circle w0.013: c16.425,62.569 r3
  circle w0.013: c16.425,62.569 r3
  circle w0.013: c16.425,62.569 r3
  circle w0.013: c16.425,62.569 r3
  circle w0.013: c16.425,62.569 r3
  circle w0.013: c16.425,62.569 r3
  circle w0.013: c44.004,58.5 r3
  circle w0.013: c44.004,58.5 r3
  circle w0.013: c44.004,58.5 r3
  circle w0.013: c44.004,58.5 r3
  circle w0.013: c44.004,58.5 r3
  circle w0.013: c44.004,58.5 r3
  circle w0.013: c112,29.973 r3.5
  circle w0.013: c112,29.973 r3.5
  circle w0.013: c112,29.973 r3.5
  circle w0.013: c112,29.973 r3.5
  circle w0.013: c35.496,55.973 r3.5
  circle w0.013: c35.496,55.973 r3.5
  circle w0.013: c3.496,3.473 r3.5
  circle w0.013: c3.496,3.473 r3.5
  circle w0.013: c74.996,3.973 r3.5
  circle w0.013: c74.996,3.973 r3.5
  circle w0.013: c108.496,9.973 r3.5
  circle w0.013: c108.496,9.973 r3.5
  circle w0.013: c77.796,58.473 r3.5
  circle w0.013: c77.796,58.473 r3.5
  circle w0.013: c42.496,17.973 r3.5
  circle w0.013: c42.496,17.973 r3.5
  circle w0.013: c20.496,36.973 r3.5
  circle w0.013: c20.496,36.973 r3.5
  circle w0.013: c74.996,3.973 r3.5
  circle w0.013: c74.996,3.973 r3.5
  circle w0.013: c16.496,60.473 r3.5
  circle w0.013: c16.496,60.473 r3.5
  circle w0.013: c42.496,17.973 r3.5
  circle w0.013: c42.496,17.973 r3.5
  circle w0.013: c16.496,60.473 r3.5
  circle w0.013: c16.496,60.473 r3.5
  circle w0.013: c35.496,55.973 r3.5
  circle w0.013: c35.496,55.973 r3.5
  circle w0.013: c20.496,36.973 r3.5
  circle w0.013: c20.496,36.973 r3.5
  circle w0.013: c108.496,9.973 r3.5
  circle w0.013: c108.496,9.973 r3.5
  circle w0.013: c3.496,3.473 r3.5
  circle w0.013: c3.496,3.473 r3.5
  circle w0.013: c77.796,58.473 r3.5
  circle w0.013: c77.796,58.473 r3.5
  circle w0.013: c42.496,17.973 r3.5
  circle w0.013: c42.496,17.973 r3.5
  circle w0.013: c20.496,36.973 r3.5
  circle w0.013: c20.496,36.973 r3.5
  circle w0.013: c112,29.973 r3.5
  circle w0.013: c112,29.973 r3.5
  circle w0.013: c35.496,55.973 r3.5
  circle w0.013: c35.496,55.973 r3.5
  circle w0.013: c16.496,60.473 r3.5
  circle w0.013: c16.496,60.473 r3.5
  circle w0.013: c108.496,9.973 r3.5
  circle w0.013: c108.496,9.973 r3.5
  circle w0.013: c77.796,58.473 r3.5
  circle w0.013: c77.796,58.473 r3.5
  circle w0.013: c3.496,3.473 r3.5
  circle w0.013: c3.496,3.473 r3.5
  circle w0.013: c74.996,3.973 r3.5
  circle w0.013: c74.996,3.973 r3.5
Top Impedance Info:
  lines w0.153: 7.489,24.375 cw(c7.727,24.137) 7.727,24.473 10.361,24.473 cw(c10.361,24.165) 10.579,24.383 ; 7.489,24.875 ccw(c7.727,25.113) 7.727,24.776 10.322,24.776 ccw(c10.322,25.141) 10.579,24.883 ; 11.579,24.383 cw(c11.801,24.161) 11.801,24.475 11.879,24.475 13.05,24.475 13.084,24.475 cw(c13.084,22.81) 14.75,22.81 14.75,21.422 ccw(c16.6,21.422) 16.6,19.572 19.033,19.572 cw(c19.033,19.138) 19.467,19.138 19.467,18.664 19.46,18.664 ; 11.579,24.883 ccw(c11.833,25.137) 11.833,24.778 11.879,24.778 13.05,24.778 13.084,24.778 cw(c13.084,22.81) 15.053,22.81 15.053,21.422 ccw(c16.6,21.422) 16.6,19.875 19.033,19.875 cw(c19.033,19.138) 19.77,19.138 19.77,18.755 ccw(c19.86,18.755) 19.86,18.664
  text "90-ohms grounded coplanar differential" at 7.452,25.664 h0.64
Bottom Placement:
  circle w0.15: c19.122,29.997 r0.95
  circle w0.15: c38.919,42.395 r0.95
  circle w0.15: c26.334,48.26 r0.95
  circle w0.15: c15.447,44.856 r0.95
  circle w0.15: c23.62,4.115 r0.95
  circle w0.15: c20.62,4.115 r0.95
  circle w0.15: c26.62,4.115 r0.95
  circle w0.15: c29.62,4.115 r0.95
  circle w0.15: c16.004,2 r0.95
  circle w0.15: c9.135,12.15 r0.95
  circle w0.15: c10.24,23.113 r0.95
  circle w0.15: c10.24,26.115 r0.95
  circle w0.15: c13.263,23.571 r0.95
  circle w0.15: c16.032,27.61 r0.95
  circle w0.15: c21.797,27.432 r0.95
  circle w0.15: c24.797,28.423 r0.95
  circle w0.15: c27.797,28.423 r0.95
  circle w0.15: c37.215,26.746 r0.95
  circle w0.15: c37.215,21.746 r0.95
  circle w0.15: c37.215,16.746 r0.95
  circle w0.15: c37.215,11.746 r0.95
  circle w0.15: c45.496,13.056 r0.95
  circle w0.15: c9.25,31.75 r0.95
  circle w0.15: c10.24,38.353 r0.95
  circle w0.15: c10.24,41.353 r0.95
  circle w0.15: c13.263,38.845 r0.95
  circle w0.15: c32.034,37.567 r0.95
  circle w0.15: c37.418,38.711 r0.95
  circle w0.15: c38.104,47.219 r0.95
  circle w0.15: c36.174,49.2 r0.95
  circle w0.15: c10.698,48.92 r0.95
  circle w0.15: c14.533,54.305 r0.95
  circle w0.15: c18.622,57.582 r0.95
  circle w0.15: c22.077,54.813 r0.95
  circle w0.15: c26.877,54.915 r0.95
  circle w0.15: c23.372,58.039 r0.95
  text "Circles mark PCA10145 v0.9.0 test point locations" at 9.793,61.805 h0.6

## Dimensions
0.029,63.5 to 12.6,58.5 on Dimension
0,0 to 8.004,5 on Dimension
0,63.856 to 12.6,58.5 on Dimension
0,0 to 8,5 on Dimension
113.104,58.5 to 106.004,5 on Dimension
44.004,5 to 106.004,5 on Dimension
8.004,5 to 44.004,5 on Dimension
44.004,58.5 to 113.104,58.5 on Dimension
12.604,58.5 to 44.004,58.5 on Dimension
0,0 to 0,63.5 on Dimension
0,0 to 117.004,0 on Dimension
